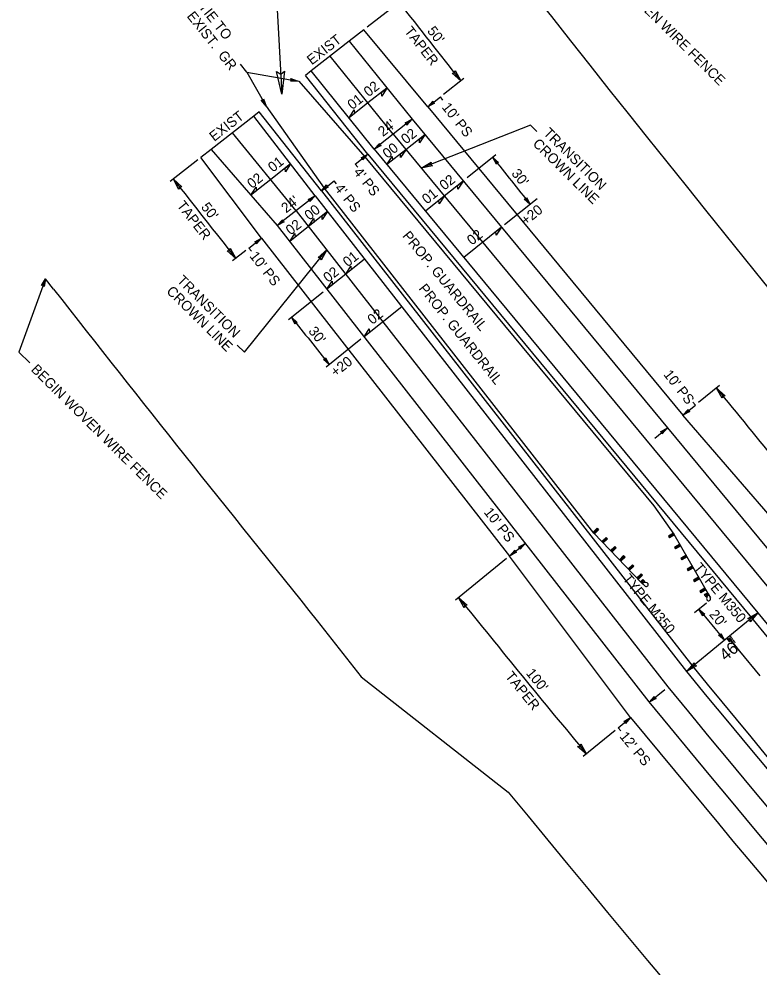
# Model space of a CAD drawing. Extents: x 1602193 to 1605074, y 908180 to 910630.
# Drawn here: x 1602213.6 to 1602582, y 909910.6 to 910382.6 of the extents above; entities that cross this region are included whole.
import ezdxf

# ---------------------------------------------------------------- set-up
doc = ezdxf.new("R2010")
doc.units = 0
for name, color, linetype in [('Prop Cable Guiderail Anchor Unit CELL', 7, 'Continuous'), ('Prop Cable Guiderail Double Face', 7, 'Continuous'), ('Prop Dimension', 7, 'Continuous'), ('Prop Dimension Text', 7, 'Continuous'), ('Prop DSN Text', 7, 'Continuous'), ('Prop EOT', 7, 'Continuous'), ('Prop Fence Woven Wire', 7, 'Continuous'), ('Prop Guardrail', 7, 'Continuous'), ('Prop Guardrail Anchor Unit CELL', 7, 'Continuous'), ('Prop Lane Lines', 7, 'Continuous'), ('Prop Paved Shoulder', 7, 'Continuous'), ('Prop Superelevation  Arrow CELL', 7, 'Continuous'), ('Prop Superelevation Label', 7, 'Continuous')]:
    doc.layers.add(name, color=color, linetype=linetype)

msp = doc.modelspace()

# ---------------------------------------------------------------- linework, layer by layer
at = {"layer": 'Prop Cable Guiderail Anchor Unit CELL'}
for p, q in [((1602565.92, 910074.21), (1602567.47, 910075.49)), ((1602567.47, 910075.49), (1602568.74, 910073.95)), ((1602565.92, 910074.21), (1602567.2, 910072.67)), ((1602566.85, 910074.01), (1602567.49, 910074.54)), ((1602566.85, 910074.01), (1602567.17, 910073.62)), ((1602567.17, 910073.62), (1602567.81, 910074.15)), ((1602572.43, 910067.91), (1602567.18, 910073.96)), ((1602567.2, 910072.67), (1602568.74, 910073.95)), ((1602572.43, 910067.91), (1602567.33, 910074.08)), ((1602567.49, 910074.54), (1602567.81, 910074.15)), ((1602572.43, 910067.91), (1602567.5, 910074.19)), ((1602582.62, 910055.58), (1602572.43, 910067.91)), ((1602572.43, 910067.91), (1602572.43, 910067.91))]:
    msp.add_line(p, q, dxfattribs=at)
at = {"layer": 'Prop Dimension'}
for p, q in [((1602404.31, 910392.09), (1602386.84, 910378.41)), ((1602435.05, 910353), (1602424.96, 910345.03)), ((1602417.11, 910338.84), (1602423.39, 910343.79)), ((1602409.25, 910332.64), (1602390.41, 910317.77)), ((1602302.62, 910312.4), (1602288.86, 910301.62)), ((1602380.99, 910310.33), (1602387.27, 910315.29)), ((1602451, 910314.86), (1602436.7, 910303.51)), ((1602364.17, 910297.06), (1602370.45, 910302.01)), ((1602361.03, 910294.58), (1602342.19, 910279.71)), ((1602471.53, 910293.03), (1602455.31, 910280.11)), ((1602328.06, 910268.56), (1602334.34, 910273.51)), ((1602326.49, 910267.32), (1602319.92, 910262.13)), ((1602365.09, 910246.66), (1602347.7, 910232.86)), ((1602383.82, 910223.11), (1602366.46, 910209.27)), ((1602562.34, 910200.1), (1602551.89, 910191.61)), ((1602544.12, 910185.31), (1602550.33, 910190.35)), ((1602530.15, 910173.96), (1602536.36, 910179)), ((1602457.85, 910115.24), (1602465.61, 910121.54)), ((1602456.29, 910113.98), (1602430.82, 910093.29)), ((1602555.9, 910091.85), (1602549.87, 910086.9)), ((1602581.38, 910086.94), (1602545.87, 910057.7)), ((1602527.35, 910042.44), (1602535.07, 910048.8)), ((1602511.91, 910029.72), (1602518.09, 910034.81)), ((1602510.37, 910028.45), (1602494.53, 910015.4))]:
    msp.add_line(p, q, dxfattribs=at)
for centre, radius, start, end in [((1613646.31, 919202), 14284.75, 218.084383, 218.283897), ((1613646.31, 919202), 14427.42, 218.084383, 218.283897), ((1613646.31, 919202), 14280.96, 219.081951, 219.480979), ((1613644.76, 919200.73), 14444.39, 219.081951, 219.480979), ((1613646.31, 919202), 14357.33, 219.401173, 219.480979)]:
    msp.add_arc(centre, radius, start, end, dxfattribs=at)
at = {"layer": 'Prop Dimension Text'}
for p, q in [((1602326.95, 910356.11), (1602323.84, 910360.02)), ((1602326.95, 910356.11), (1602336.7, 910339.11)), ((1602326.95, 910356.11), (1602352.55, 910351.53)), ((1602424.62, 910342.22), (1602423.39, 910343.79)), ((1602468.2, 910329.66), (1602413.84, 910308.27)), ((1602471.4, 910326.5), (1602468.2, 910329.66)), ((1602382.23, 910308.76), (1602380.99, 910310.33)), ((1602371.69, 910300.44), (1602370.45, 910302.01)), ((1602325.8, 910216.68), (1602366.87, 910267.58)), ((1602329.3, 910266.99), (1602328.06, 910268.56)), ((1602322.25, 910220.2), (1602325.8, 910216.68)), ((1602549.07, 910191.9), (1602550.33, 910190.35)), ((1602513.18, 910028.18), (1602511.91, 910029.72))]:
    msp.add_line(p, q, dxfattribs=at)
for radius in [14295.92, 14423.81]:
    msp.add_arc((1613646.31, 919202), radius, 218.443508, 218.563216, dxfattribs=at)
at = {"layer": 'Prop DSN Text'}
for p, q in [((1602337.24, 910480.07), (1602344.4, 910345.15)), ((1602226.72, 910253.28), (1602213.58, 910216.7)), ((1602213.58, 910216.7), (1602218.91, 910211.41))]:
    msp.add_line(p, q, dxfattribs=at)
for points in [[(1602345.79, 910356.64), (1602344.4, 910345.15), (1602341.8, 910356.43), (1602343.87, 910355.14)], [(1602430.73, 910356.86), (1602433.48, 910351.76), (1602429.16, 910355.62), (1602430.38, 910355.69)], [(1602348.92, 910352.86), (1602352.55, 910351.53), (1602348.69, 910351.55), (1602349.27, 910352.12)], [(1602335.39, 910342.74), (1602336.7, 910339.11), (1602334.23, 910342.08), (1602335.04, 910342.01)], [(1602420.5, 910340.67), (1602417.11, 910338.84), (1602419.68, 910341.71), (1602419.72, 910340.9)], [(1602405.86, 910330.81), (1602409.25, 910332.64), (1602406.68, 910329.76), (1602406.64, 910330.57)], [(1602393.81, 910319.6), (1602390.41, 910317.77), (1602392.98, 910320.64), (1602393.03, 910319.83)], [(1602383.87, 910313.45), (1602387.27, 910315.29), (1602384.7, 910312.41), (1602384.65, 910313.22)], [(1602451.27, 910310.22), (1602449.43, 910313.61), (1602452.32, 910311.05), (1602451.5, 910311)], [(1602419.51, 910309.43), (1602413.84, 910308.27), (1602418.78, 910311.29), (1602418.49, 910310.1)], [(1602293.16, 910297.75), (1602290.43, 910302.86), (1602294.74, 910298.98), (1602293.52, 910298.92)], [(1602367.57, 910298.89), (1602364.17, 910297.06), (1602366.74, 910299.93), (1602366.79, 910299.12)], [(1602357.63, 910292.74), (1602361.03, 910294.58), (1602358.46, 910291.7), (1602358.41, 910292.51)], [(1602466.18, 910293.63), (1602468.02, 910290.24), (1602465.13, 910292.8), (1602465.95, 910292.85)], [(1602345.59, 910281.54), (1602342.19, 910279.71), (1602344.76, 910282.59), (1602344.81, 910281.77)], [(1602330.95, 910271.68), (1602334.34, 910273.51), (1602331.77, 910270.63), (1602331.73, 910271.45)], [(1602318.74, 910268.46), (1602321.49, 910263.37), (1602317.17, 910267.22), (1602318.39, 910267.29)], [(1602362.51, 910263.77), (1602366.87, 910267.58), (1602364.07, 910262.52), (1602363.73, 910263.69)], [(1602224.81, 910249.92), (1602226.72, 910253.28), (1602226.06, 910249.47), (1602225.6, 910250.14)], [(1602351.11, 910230.71), (1602349.27, 910234.1), (1602352.15, 910231.54), (1602351.34, 910231.49)], [(1602366.18, 910213.91), (1602368.03, 910210.52), (1602365.14, 910213.08), (1602365.95, 910213.13)], [(1602563.6, 910193.78), (1602560.79, 910198.84), (1602565.16, 910195.04), (1602563.94, 910194.96)], [(1602547.5, 910187.19), (1602544.12, 910185.31), (1602546.66, 910188.22), (1602546.71, 910187.41)], [(1602532.99, 910177.12), (1602536.36, 910179), (1602533.83, 910176.09), (1602533.77, 910176.9)], [(1602461.22, 910117.12), (1602457.85, 910115.24), (1602460.38, 910118.15), (1602460.44, 910117.34)], [(1602462.24, 910119.66), (1602465.61, 910121.54), (1602463.08, 910118.63), (1602463.02, 910119.44)], [(1602435.19, 910089.48), (1602432.38, 910094.54), (1602436.75, 910090.74), (1602435.53, 910090.66)], [(1602554, 910085.38), (1602552.11, 910088.74), (1602555.03, 910086.23), (1602554.22, 910086.16)], [(1602576.34, 910084.09), (1602581.38, 910086.94), (1602577.61, 910082.55), (1602577.52, 910083.76)], [(1602562.91, 910076.66), (1602564.81, 910073.3), (1602561.88, 910075.81), (1602562.69, 910075.87)], [(1602550.91, 910060.55), (1602545.87, 910057.7), (1602549.64, 910062.1), (1602549.73, 910060.88)], [(1602530.71, 910044.34), (1602527.35, 910042.44), (1602529.86, 910045.37), (1602529.92, 910044.56)], [(1602514.73, 910032.9), (1602518.09, 910034.81), (1602515.58, 910031.88), (1602515.51, 910032.69)], [(1602493.21, 910021.71), (1602496.07, 910016.68), (1602491.67, 910020.44), (1602492.88, 910020.54)]]:
    msp.add_lwpolyline(points, close=True, dxfattribs=at)
at = {"layer": 'Prop EOT'}
for p, q in [((1602377.98, 910371.47), (1602359.1, 910356.67)), ((1602377.98, 910371.47), (1602409.25, 910332.64)), ((1602390.41, 910317.77), (1602359.1, 910356.67)), ((1602330.51, 910334.26), (1602309.3, 910317.64)), ((1602361.03, 910294.58), (1602330.51, 910334.26)), ((1602409.25, 910332.64), (1602599.88, 910102.22)), ((1602309.3, 910317.64), (1602342.19, 910279.71)), ((1602390.41, 910317.77), (1602581.38, 910086.94)), ((1602361.03, 910294.58), (1602545.87, 910057.7)), ((1602342.19, 910279.71), (1602527.15, 910042.68))]:
    msp.add_line(p, q, dxfattribs=at)
for radius, start, end in [(14335.86, 219.480979, 227.66104), (14381.86, 219.480979, 227.66104), (14405.86, 219.479716, 227.662303)]:
    msp.add_arc((1613646.31, 919202), radius, start, end, dxfattribs=at)
at = {"layer": 'Prop Fence Woven Wire'}
for p, q in [((1602230.79, 910248.08), (1602226.72, 910253.28)), ((1602362.09, 910082.97), (1602383.88, 910055.16)), ((1602383.88, 910055.16), (1602457.18, 909997.71))]:
    msp.add_line(p, q, dxfattribs=at)
for centre, radius, start, end in [((1613597.21, 919158.4), 14163.95, 218.093461, 222.076817), ((1613601.21, 919155.46), 14443.95, 218.074505, 218.911306), ((1613600.64, 919155.95), 14423.95, 219.415042, 223.36309)]:
    msp.add_arc(centre, radius, start, end, dxfattribs=at)
at = {"layer": 'Prop Guardrail'}
for p, q in [((1602352.87, 910351.65), (1602385.79, 910313.94)), ((1602365.76, 910298.27), (1602336.85, 910339.14)), ((1602385.79, 910313.94), (1602529.55, 910140.17)), ((1602499.69, 910126.64), (1602365.76, 910298.27)), ((1602529.55, 910140.17), (1602539.66, 910126.16))]:
    msp.add_line(p, q, dxfattribs=at)
at = {"layer": 'Prop Guardrail Anchor Unit CELL'}
for p, q in [((1602499.34, 910127), (1602501.45, 910129.04)), ((1602500.03, 910126.28), (1602502.15, 910128.32)), ((1602500.42, 910128.04), (1602500.03, 910126.28)), ((1602502.15, 910128.32), (1602500.42, 910128.04)), ((1602500.42, 910128.04), (1602501.11, 910127.32)), ((1602501.11, 910127.32), (1602501.45, 910129.04)), ((1602501.45, 910129.04), (1602502.15, 910128.32)), ((1602499.34, 910127), (1602501.11, 910127.32)), ((1602499.69, 910126.64), (1602523.55, 910101.96)), ((1602503.72, 910122.47), (1602505.83, 910124.51)), ((1602503.72, 910122.47), (1602505.49, 910122.79)), ((1602504.41, 910121.75), (1602506.53, 910123.79)), ((1602504.8, 910123.51), (1602504.41, 910121.75)), ((1602506.53, 910123.79), (1602504.8, 910123.51)), ((1602504.8, 910123.51), (1602505.49, 910122.79)), ((1602505.49, 910122.79), (1602505.83, 910124.51)), ((1602505.83, 910124.51), (1602506.53, 910123.79)), ((1602539.41, 910126.59), (1602536.86, 910125.13)), ((1602538.6, 910124.98), (1602536.86, 910125.13)), ((1602536.86, 910125.13), (1602537.35, 910124.27)), ((1602537.35, 910124.27), (1602538.11, 910125.85)), ((1602539.91, 910125.72), (1602537.35, 910124.27)), ((1602538.11, 910125.85), (1602538.6, 910124.98)), ((1602538.11, 910125.85), (1602539.91, 910125.72)), ((1602539.41, 910126.59), (1602538.6, 910124.98)), ((1602539.66, 910126.16), (1602556.67, 910096.35)), ((1602508.1, 910117.94), (1602510.21, 910119.98)), ((1602508.1, 910117.94), (1602509.87, 910118.27)), ((1602508.79, 910117.22), (1602510.91, 910119.26)), ((1602509.18, 910118.98), (1602508.79, 910117.22)), ((1602510.91, 910119.26), (1602509.18, 910118.98)), ((1602509.18, 910118.98), (1602509.87, 910118.27)), ((1602509.87, 910118.27), (1602510.21, 910119.98)), ((1602510.21, 910119.98), (1602510.91, 910119.26)), ((1602542.53, 910121.12), (1602539.98, 910119.66)), ((1602541.72, 910119.51), (1602539.98, 910119.66)), ((1602539.98, 910119.66), (1602540.48, 910118.79)), ((1602540.48, 910118.79), (1602541.23, 910120.37)), ((1602543.03, 910120.25), (1602540.48, 910118.79)), ((1602541.23, 910120.37), (1602541.72, 910119.51)), ((1602541.23, 910120.37), (1602543.03, 910120.25)), ((1602542.53, 910121.12), (1602541.72, 910119.51)), ((1602512.48, 910113.41), (1602514.59, 910115.45)), ((1602512.48, 910113.41), (1602514.25, 910113.74)), ((1602513.17, 910112.69), (1602515.29, 910114.74)), ((1602513.56, 910114.45), (1602513.17, 910112.69)), ((1602515.29, 910114.74), (1602513.56, 910114.45)), ((1602513.56, 910114.45), (1602514.25, 910113.74)), ((1602514.25, 910113.74), (1602514.59, 910115.45)), ((1602514.59, 910115.45), (1602515.29, 910114.74)), ((1602545.65, 910115.65), (1602543.1, 910114.19)), ((1602544.85, 910114.04), (1602543.1, 910114.19)), ((1602543.1, 910114.19), (1602543.6, 910113.32)), ((1602543.6, 910113.32), (1602544.35, 910114.9)), ((1602546.15, 910114.78), (1602543.6, 910113.32)), ((1602544.35, 910114.9), (1602544.85, 910114.04)), ((1602544.35, 910114.9), (1602546.15, 910114.78)), ((1602545.65, 910115.65), (1602544.85, 910114.04)), ((1602516.86, 910108.88), (1602518.97, 910110.93)), ((1602516.86, 910108.88), (1602518.63, 910109.21)), ((1602517.55, 910108.17), (1602519.66, 910110.21)), ((1602517.93, 910109.93), (1602517.55, 910108.17)), ((1602519.66, 910110.21), (1602517.93, 910109.93)), ((1602517.93, 910109.93), (1602518.63, 910109.21)), ((1602518.63, 910109.21), (1602518.97, 910110.93)), ((1602518.97, 910110.93), (1602519.66, 910110.21)), ((1602548.78, 910110.17), (1602546.23, 910108.72)), ((1602547.97, 910108.56), (1602546.23, 910108.72)), ((1602546.23, 910108.72), (1602546.72, 910107.85)), ((1602546.72, 910107.85), (1602547.47, 910109.43)), ((1602549.27, 910109.31), (1602546.72, 910107.85)), ((1602547.47, 910109.43), (1602547.97, 910108.56)), ((1602547.47, 910109.43), (1602549.27, 910109.31)), ((1602548.78, 910110.17), (1602547.97, 910108.56)), ((1602521.24, 910104.36), (1602523.35, 910106.4)), ((1602521.24, 910104.36), (1602523.01, 910104.68)), ((1602521.58, 910103.99), (1602522.12, 910104.52)), ((1602521.93, 910103.64), (1602524.04, 910105.68)), ((1602522.31, 910105.4), (1602521.93, 910103.64)), ((1602524.04, 910105.68), (1602522.31, 910105.4)), ((1602522.31, 910105.4), (1602523.01, 910104.68)), ((1602523.01, 910104.68), (1602523.35, 910106.4)), ((1602523.35, 910106.4), (1602524.04, 910105.68)), ((1602551.9, 910104.7), (1602549.35, 910103.25)), ((1602549.84, 910102.38), (1602550.6, 910103.96)), ((1602552.39, 910103.83), (1602549.84, 910102.38)), ((1602550.6, 910103.96), (1602551.09, 910103.09)), ((1602550.6, 910103.96), (1602552.39, 910103.83)), ((1602551.9, 910104.7), (1602551.09, 910103.09)), ((1602524.22, 910103.59), (1602523.06, 910102.46)), ((1602523.06, 910102.46), (1602525.2, 910102.58)), ((1602523.55, 910101.96), (1602524.14, 910102.53)), ((1602523.55, 910101.96), (1602525.07, 910100.38)), ((1602524.03, 910101.46), (1602524.22, 910103.59)), ((1602524.03, 910101.46), (1602525.2, 910102.58)), ((1602524.03, 910101.46), (1602524.54, 910101.95)), ((1602524.03, 910101.46), (1602524.54, 910101.95)), ((1602525.2, 910102.58), (1602524.22, 910103.59)), ((1602525.66, 910102.06), (1602524.54, 910101.95)), ((1602551.09, 910103.09), (1602549.35, 910103.25)), ((1602549.35, 910103.25), (1602549.84, 910102.38)), ((1602555.02, 910099.23), (1602552.47, 910097.77)), ((1602555.02, 910099.23), (1602554.22, 910097.62)), ((1602554.22, 910097.62), (1602552.47, 910097.77)), ((1602552.47, 910097.77), (1602552.97, 910096.91)), ((1602552.97, 910096.91), (1602553.72, 910098.49)), ((1602555.52, 910098.36), (1602552.97, 910096.91)), ((1602553.72, 910098.49), (1602554.22, 910097.62)), ((1602553.72, 910098.49), (1602555.52, 910098.36)), ((1602555.27, 910098.8), (1602554.62, 910098.43)), ((1602554.92, 910096.16), (1602556.32, 910096.96)), ((1602555.61, 910094.94), (1602554.92, 910096.16)), ((1602557.02, 910095.74), (1602554.92, 910096.16)), ((1602556.32, 910096.96), (1602555.61, 910094.94)), ((1602557.02, 910095.74), (1602555.61, 910094.94)), ((1602556.67, 910096.35), (1602555.95, 910095.94)), ((1602555.99, 910094.35), (1602556.4, 910095.39)), ((1602557.02, 910095.74), (1602556.4, 910095.39)), ((1602557.02, 910095.74), (1602556.4, 910095.39)), ((1602556.67, 910096.35), (1602557.76, 910094.45))]:
    msp.add_line(p, q, dxfattribs=at)
for centre, major_axis, start_param, end_param in [((1602525.79, 910101.07), (0.714, 0.69), 3.141593, 7.214552), ((1602556.89, 910093.95), (0.862, 0.492), 2.210226, 6.283185)]:
    msp.add_ellipse(centre, major_axis=major_axis, ratio=0.995379, start_param=start_param, end_param=end_param, dxfattribs=at)
at = {"layer": 'Prop Lane Lines'}
for p, q in [((1602399.83, 910325.2), (1602368.54, 910364.07)), ((1602351.61, 910287.14), (1602319.9, 910325.95)), ((1602399.83, 910325.2), (1602590.64, 910094.57)), ((1602351.61, 910287.14), (1602536.61, 910050.07))]:
    msp.add_line(p, q, dxfattribs=at)
msp.add_arc((1613646.31, 919202), 14393.86, 219.480979, 227.66104, dxfattribs=at)
at = {"layer": 'Prop Paved Shoulder'}
for p, q in [((1602385.27, 910377.18), (1602377.98, 910371.47)), ((1602417.11, 910338.84), (1602385.27, 910377.18)), ((1602359.1, 910356.67), (1602356.26, 910354.44)), ((1602387.27, 910315.29), (1602356.26, 910354.44)), ((1602333.13, 910336.32), (1602330.51, 910334.26)), ((1602364.17, 910297.06), (1602333.13, 910336.32)), ((1602417.11, 910338.84), (1602544.12, 910185.31)), ((1602309.3, 910317.64), (1602304.19, 910313.64)), ((1602334.34, 910273.51), (1602304.19, 910313.64)), ((1602387.27, 910315.29), (1602578.29, 910084.4)), ((1602364.17, 910297.06), (1602548.99, 910060.2)), ((1602334.34, 910273.51), (1602457.85, 910115.24)), ((1602609.16, 910109.83), (1602544.12, 910185.31)), ((1602518.09, 910034.81), (1602457.85, 910115.24))]:
    msp.add_line(p, q, dxfattribs=at)
for radius, start, end in [(14339.86, 219.480979, 222.863015), (14377.86, 219.48119, 222.373049), (14417.86, 219.480979, 222.382421)]:
    msp.add_arc((1613646.31, 919202), radius, start, end, dxfattribs=at)
at = {"layer": 'Prop Superelevation  Arrow CELL'}
for p, q in [((1602396.75, 910348.17), (1602387.32, 910340.75)), ((1602387.32, 910340.75), (1602377.89, 910333.33)), ((1602415.61, 910324.96), (1602406.19, 910317.51)), ((1602406.19, 910317.51), (1602396.78, 910310.07)), ((1602348.82, 910310.45), (1602338.93, 910302.66)), ((1602338.93, 910302.66), (1602329.04, 910294.88)), ((1602434.68, 910301.91), (1602425.28, 910294.44)), ((1602425.28, 910294.44), (1602415.88, 910286.98)), ((1602367.19, 910286.68), (1602357.78, 910279.24)), ((1602357.78, 910279.24), (1602348.36, 910271.8)), ((1602453.75, 910278.86), (1602434.98, 910263.89)), ((1602385.67, 910263), (1602376.27, 910255.54)), ((1602376.27, 910255.54), (1602366.87, 910248.08)), ((1602404.15, 910239.32), (1602385.38, 910224.36))]:
    msp.add_line(p, q, dxfattribs=at)
for points in [[(1602396.75, 910348.17), (1602394.14, 910344.21), (1602394.02, 910346.02)], [(1602377.89, 910333.33), (1602380.5, 910337.29), (1602380.61, 910335.47)], [(1602415.61, 910324.96), (1602413.01, 910320.99), (1602412.89, 910322.8)], [(1602406.19, 910317.51), (1602403.59, 910313.54), (1602403.47, 910315.36)], [(1602396.78, 910310.07), (1602399.38, 910314.04), (1602399.5, 910312.22)], [(1602348.82, 910310.45), (1602346.21, 910306.49), (1602346.1, 910308.3)], [(1602329.04, 910294.88), (1602331.64, 910298.84), (1602331.76, 910297.02)], [(1602434.68, 910301.91), (1602432.09, 910297.93), (1602431.96, 910299.75)], [(1602425.28, 910294.44), (1602422.69, 910290.47), (1602422.56, 910292.29)], [(1602357.78, 910279.24), (1602360.38, 910283.21), (1602360.5, 910281.39)], [(1602367.19, 910286.68), (1602364.59, 910282.72), (1602364.47, 910284.53)], [(1602453.75, 910278.86), (1602451.17, 910274.88), (1602451.04, 910276.7)], [(1602348.36, 910271.8), (1602350.96, 910275.77), (1602351.08, 910273.95)], [(1602376.27, 910255.54), (1602378.86, 910259.51), (1602378.99, 910257.7)], [(1602366.87, 910248.08), (1602369.47, 910252.05), (1602369.59, 910250.23)], [(1602385.38, 910224.36), (1602387.97, 910228.33), (1602388.1, 910226.52)]]:
    msp.add_lwpolyline(points, close=True, dxfattribs=at)

# ---------------------------------------------------------------- texts
at = {"layer": 'Prop Cable Guiderail Double Face'}
for rotation, p in [(309.4464, (1602404.16, 910274.46)), (308.6334, (1602412.3, 910248.28))]:
    msp.add_text('PROP. GUARDRAIL', height=5, rotation=rotation, dxfattribs=at).set_placement(p)
at = {"layer": 'Prop Dimension'}
for s, rotation, p in [("24'", 38.2839, (1602394.78, 910323.76)), ('TAPER', 308.1742, (1602291.9, 910289.64)), ("24'", 38.2839, (1602346.58, 910285.72)), ("50'", 308.1807, (1602303.98, 910288.83)), ("20'", 309.4414, (1602556.91, 910086.04)), ('TAPER', 309.2854, (1602455.36, 910055.25)), ("100'", 309.2847, (1602465.72, 910056.79))]:
    msp.add_text(s, height=5, rotation=rotation, dxfattribs=at).set_placement(p)
at = {"layer": 'Prop Dimension Text'}
for s, height, rotation, p in [('TIE TO', 5, 308.4898, (1602302.76, 910388.55)), ('EXIST.  GR', 5, 308.4898, (1602296.89, 910383.88)), ('TAPER', 5, 308.1813, (1602405.16, 910376.42)), ("50'", 5, 308.1833, (1602416.53, 910376.52)), ("10' PS", 5, 308.2839, (1602423.83, 910338.55)), ('TRANSITION', 5, 315.2976, (1602474.29, 910325.4)), ('CROWN LINE', 5, 315.2976, (1602469.01, 910320.07)), ("4' PS", 5, 308.2839, (1602379.86, 910306.26)), ("30'", 5, 308.5051, (1602458.47, 910305.56)), ("4' PS", 5, 308.2839, (1602370.44, 910298.19)), ('+20', 5, 38.5632, (1602465.92, 910279.61)), ("10' PS", 5, 308.2839, (1602328.1, 910264.45)), ('TRANSITION', 5, 315.2976, (1602291.92, 910251.98)), ('CROWN LINE', 5, 315.2976, (1602286.64, 910246.65)), ("30'", 5, 308.5053, (1602357.41, 910227.07)), ('+20', 5, 38.5632, (1602371.21, 910204.1)), ("10' PS", 5, 308.2839, (1602534.18, 910205.52)), ("10' PS", 5, 308.2839, (1602444.75, 910136.94)), ("46'", 6, 39.481, (1602565.35, 910062.68)), ("12' PS", 5, 309.481, (1602512.28, 910025.3))]:
    msp.add_text(s, height=height, rotation=rotation, dxfattribs=at).set_placement(p)
at = {"layer": 'Prop DSN Text'}
for p in [(1602497.02, 910413.62), (1602219.23, 910207.7)]:
    msp.add_text('BEGIN WOVEN WIRE FENCE', height=5, rotation=315.2976, dxfattribs=at).set_placement(p)
at = {"layer": 'Prop Guardrail Anchor Unit CELL'}
for p in [(1602549.2, 910109.28), (1602513.83, 910103.77)]:
    msp.add_text('TYPE M350', height=5, rotation=309.6024, dxfattribs=at).set_placement(p)
at = {"layer": 'Prop Superelevation Label'}
for s, rotation, p in [('EXIST', 38.0844, (1602359.37, 910359.42)), ('02', 38.2041, (1602387.64, 910343.57)), ('01', 38.2041, (1602379.53, 910337.17)), ('EXIST', 38.0844, (1602310.8, 910321.36)), ('02', 38.3238, (1602406.24, 910320.04)), ('00', 38.3238, (1602397.06, 910312.84)), ('01', 38.2041, (1602340, 910306.05)), ('02', 38.2041, (1602329.61, 910297.88)), ('02', 38.4435, (1602425.39, 910297.06)), ('01', 38.4435, (1602416.67, 910290.16)), ('00', 38.3238, (1602358.15, 910282.08)), ('02', 38.3238, (1602348.83, 910274.72)), ('02', 38.5632, (1602439.06, 910269.7)), ('01', 38.4435, (1602377.27, 910258.88)), ('02', 38.4435, (1602367.51, 910251.14)), ('02', 38.5632, (1602389.53, 910230.22))]:
    msp.add_text(s, height=5, rotation=rotation, dxfattribs=at).set_placement(p)

doc.saveas('drawing.dxf')
